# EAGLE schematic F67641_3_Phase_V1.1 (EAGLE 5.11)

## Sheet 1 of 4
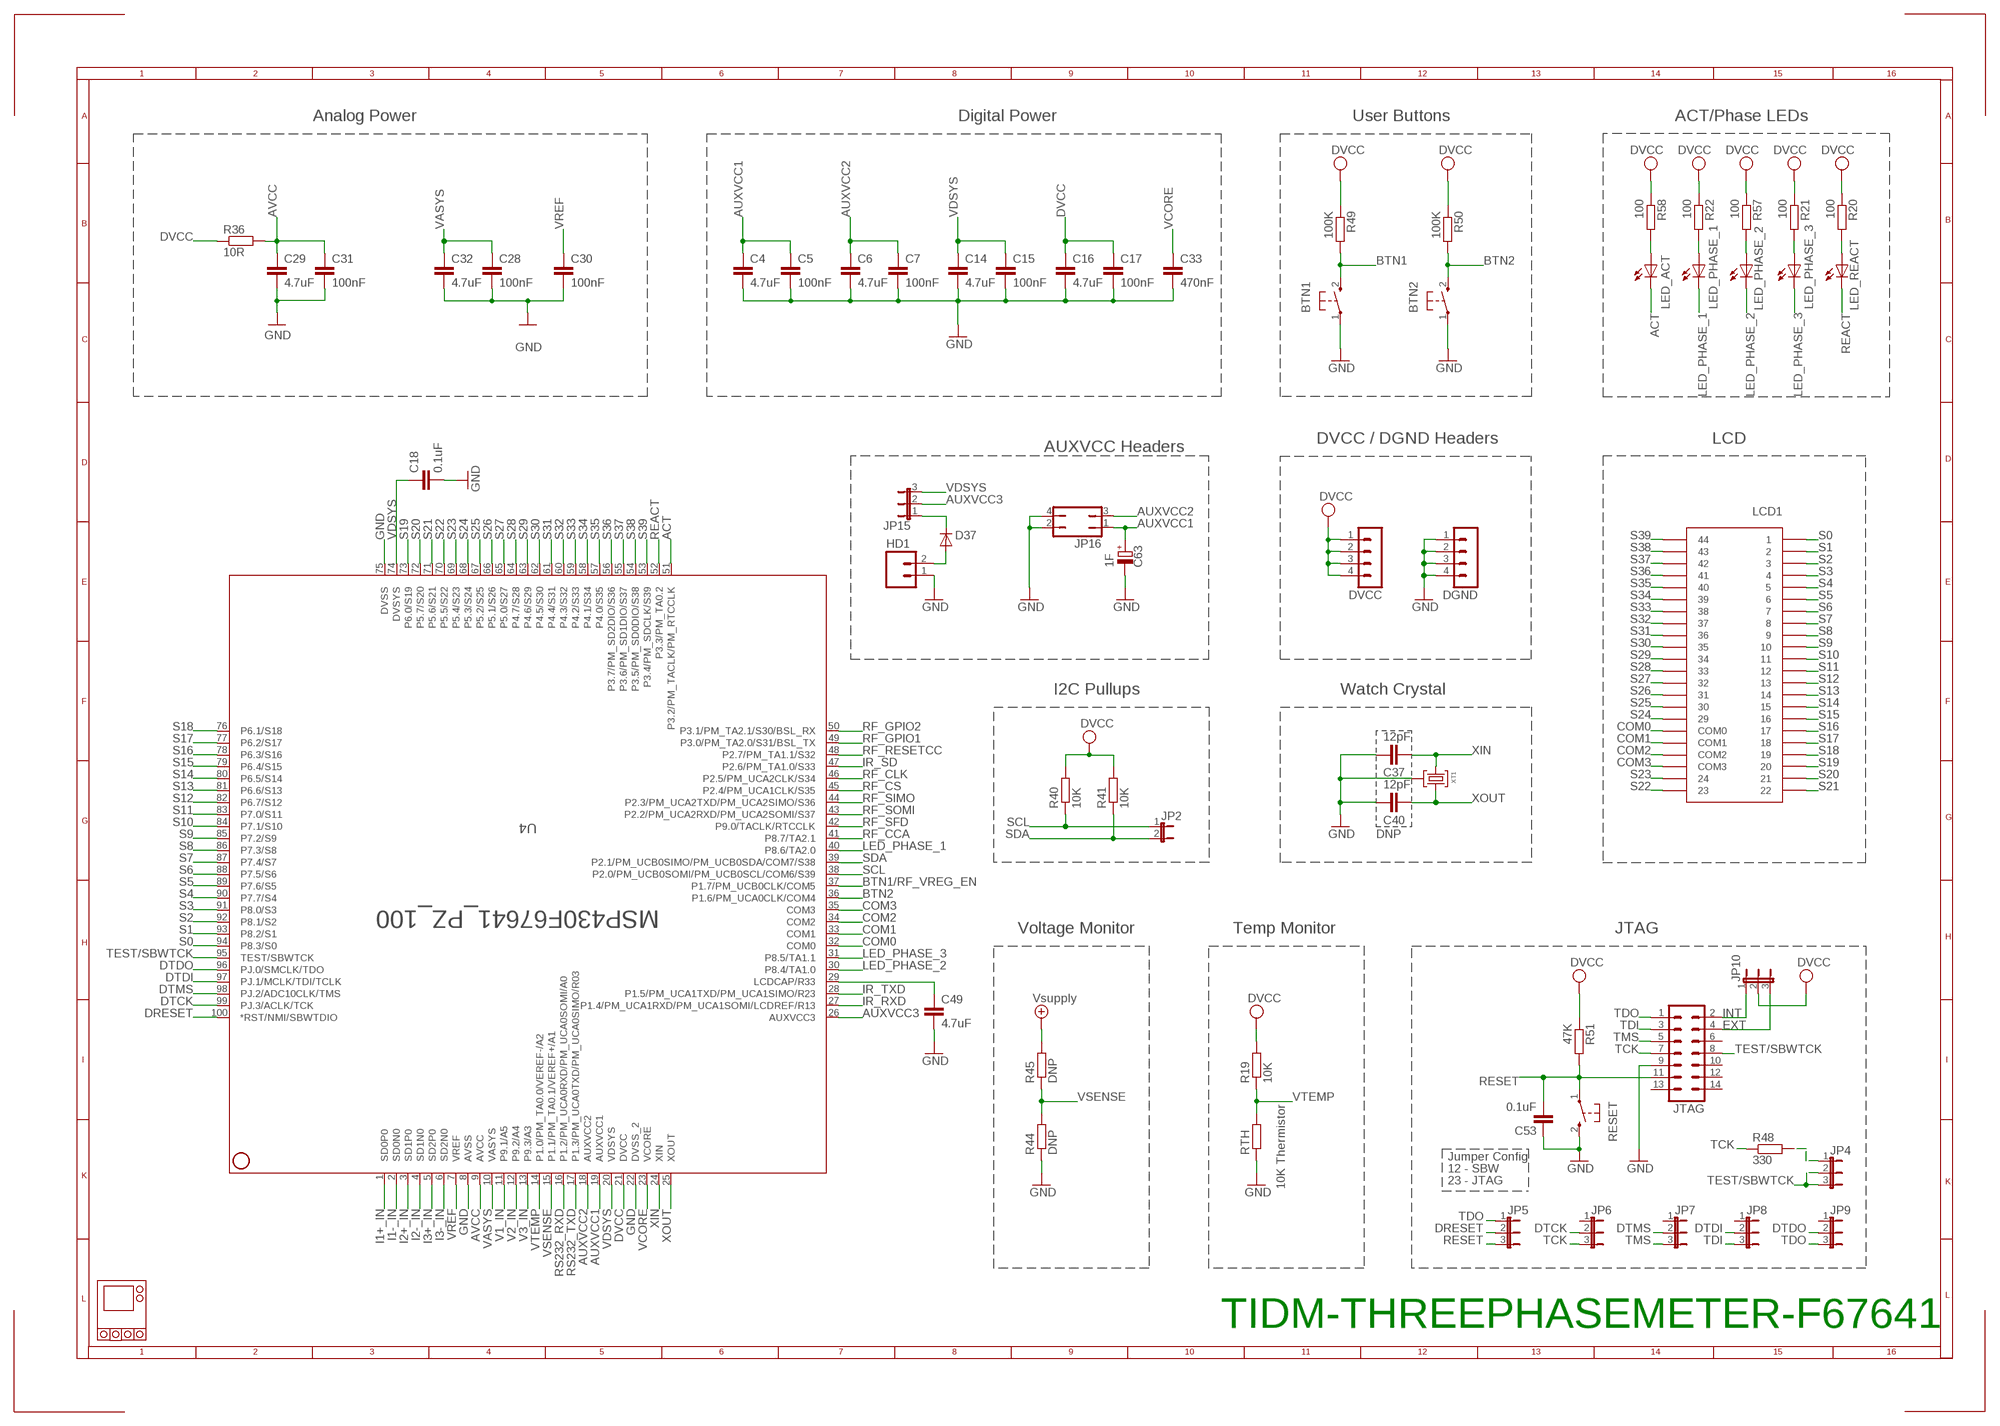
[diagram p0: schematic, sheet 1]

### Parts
BTN1  PB  [PBTH]
BTN2  PB  [PBTH]
C4  4.7uF  C-EUC0603  [C0603]
C5  100nF  C-EUC0603  [C0603]
C6  4.7uF  C-EUC0603  [C0603]
C7  100nF  C-EUC0603  [C0603]
C14  4.7uF  C-EUC0603  [C0603]
C15  100nF  C-EUC0603  [C0603]
C16  4.7uF  C-EUC0603  [C0603]
C17  100nF  C-EUC0603  [C0603]
C18  0.1uF  C-EUC0603  [C0603]
C28  100nF  C-EUC0603  [C0603]
C29  4.7uF  C-EUC0603  [C0603]
C30  100nF  C-EUC0603  [C0603]
C31  100nF  C-EUC0603  [C0603]
C32  4.7uF  C-EUC0603  [C0603]
C33  470nF  C-EUC0603  [C0603]
C37  12pF  C-EUC0603  [C0603]
C40  12pF  C-EUC0603  [C0603]
C49  4.7uF  C-EUC0603  [C0603]
C53  0.1uF  C-EUC0603  [C0603]
C63  1F  SUPERCAP  [SUPERCAP]
CASE1  3_PHASE_CASE  [3_PHASE_CASE]
D37  PMLL4148  [SOD80C]
DGND  MA04-1  [MA04-1]
DVCC  MA04-1  [MA04-1]
HD1  M02PTH  [1X02]
JP2  JP1E  [JP1]
JP4  JP2E  [JP2]
JP5  JP2E  [JP2]
JP6  JP2E  [JP2]
JP7  JP2E  [JP2]
JP8  JP2E  [JP2]
JP9  JP2E  [JP2]
JP10  JP2E  [JP2]
JP15  JP2E  [JP2]
JP16  JP2Q  [JP2Q]
JTAG  ML14  [ML14]
LCD1  TI_160SEG_LCD  [TI_160SEG_LCD]
LED_ACT  LED3MM  [LED3MM]
LED_PHASE_1  LED3MM  [LED3MM]
LED_PHASE_2  LED3MM  [LED3MM]
LED_PHASE_3  LED3MM  [LED3MM]
LED_REACT  LED3MM  [LED3MM]
R19  10K  R-EU_R0603  [R0603]
R20  100  R-EU_R0603  [R0603]
R21  100  R-EU_R0603  [R0603]
R22  100  R-EU_R0603  [R0603]
R36  10R  R-EU_R0805  [R0805]
R40  10K  R-EU_R0603  [R0603]
R41  10K  R-EU_R0603  [R0603]
R44  DNP  R-EU_R0603  [R0603]
R45  DNP  R-EU_R0603  [R0603]
R48  330  R-EU_R0603  [R0603]
R49  100K  R-EU_R0603  [R0603]
R50  100K  R-EU_R0603  [R0603]
R51  47K  R-EU_R0603  [R0603]
R57  100  R-EU_R0603  [R0603]
R58  100  R-EU_R0603  [R0603]
RESET  PB  [PBTH]
RTH  10K Thermistor  R-EU_R0603  [R0603]
U4  MSP430F67641_PZ_100  [PZ100]
XT1  CM200T  [CM200T]

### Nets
ACT: LED_ACT.K(C) U4.51(P3.2/PM_TACLK/PM_RTCCLK) ; also sheet 4
AUXVCC1: C4.1 C5.1 C63.VCC(+) JP16.1 U4.19(AUXVCC1)
AUXVCC2: C6.1 C7.1 JP16.3 U4.18(AUXVCC2)
AUXVCC3: JP15.2 U4.26(AUXVCC3)
AVCC: C29.1 C31.1 R36.2 U4.9(AVCC) ; also sheet 2
BTN1: BTN1.2(S) R49.2 ; also sheet 4
BTN1/RF_VREG_EN: U4.37(P1.7/PM_UCB0CLK/COM5) ; also sheet 4
BTN2: BTN2.2(S) R50.2 U4.36(P1.6/PM_UCA0CLK/COM4)
COM0: LCD1.COM0 U4.32(COM0)
COM1: LCD1.COM1 U4.33(COM1)
COM2: LCD1.COM2 U4.34(COM2)
COM3: LCD1.COM3 U4.35(COM3)
DRESET: JP5.2 U4.100(*RST/NMI/SBWTDIO)
DTCK: JP6.2 U4.99(PJ.3/ACLK/TCK)
DTDI: JP8.2 U4.97(PJ.1/MCLK/TDI/TCLK)
DTDO: JP9.2 U4.96(PJ.0/SMCLK/TDO)
DTMS: JP7.2 U4.98(PJ.2/ADC10CLK/TMS)
DVCC: C16.1 C17.1 DVCC.1 DVCC.2 DVCC.3 DVCC.4 JP10.2 R19.2 R20.1 R21.1 R22.1 R36.1 R40.2 R41.2 R49.1 R50.1 R51.1 R57.1 R58.1 U4.21(DVCC) ; also sheet 3,4
EXT: JP10.3 JTAG.4
GND: BTN1.1(P) BTN2.1(P) C4.2 C5.2 C6.2 C7.2 C14.2 C15.2 C16.2 C17.2 C18.2 C28.2 C29.2 C30.2 C31.2 C32.2 C33.2 C37.2 C40.2 C49.2 C53.1 C63.GND(-) DGND.1 DGND.2 DGND.3 DGND.4 HD1.1 JP16.2 JP16.4 JTAG.9 R44.1 RESET.2(S) RTH.1 U4.8(AVSS) U4.22(DVSS_2) U4.75(DVSS) XT1.P3 ; also sheet 2,3,4
I1+_IN: U4.1(SD0P0) ; also sheet 2
I1-_IN: U4.2(SD0N0) ; also sheet 2
I2+_IN: U4.3(SD1P0) ; also sheet 2
I2-_IN: U4.4(SD1N0) ; also sheet 2
I3+_IN: U4.5(SD2P0) ; also sheet 2
I3-_IN: U4.6(SD2N0) ; also sheet 2
INT: JP10.1 JTAG.2
IR_RXD: U4.27(P1.4/PM_UCA1RXD/PM_UCA1SOMI/LCDREF/R13) ; also sheet 4
IR_SD: U4.47(P2.6/PM_TA1.0/S33) ; also sheet 4
IR_TXD: U4.28(P1.5/PM_UCA1TXD/PM_UCA1SIMO/R23) ; also sheet 4
LED_PHASE_1: LED_PHASE_1.K(C) U4.40(P8.6/TA2.0)
LED_PHASE_2: LED_PHASE_2.K(C) U4.30(P8.4/TA1.0)
LED_PHASE_3: LED_PHASE_3.K(C) U4.31(P8.5/TA1.1)
N$4: C49.1 U4.29(LCDCAP/R33)
N$5: LED_REACT.A R20.2
N$6: LED_PHASE_3.A R21.2
N$7: LED_PHASE_1.A R22.2
N$10: JP4.1 R48.2
N$33: D37.C JP15.1
N$34: D37.A HD1.2
N$44: LED_ACT.A R58.2
N$46: LED_PHASE_2.A R57.2
REACT: LED_REACT.K(C) U4.52(P3.3/PM_TA0.2) ; also sheet 4
RESET: C53.2 JP5.3 JTAG.11 R51.2 RESET.1(P)
RF_CCA: U4.41(P8.7/TA2.1) ; also sheet 4
RF_CLK: U4.46(P2.5/PM_UCA2CLK/S34) ; also sheet 4
RF_CS: U4.45(P2.4/PM_UCA1CLK/S35) ; also sheet 4
RF_GPIO1: U4.49(P3.0/PM_TA2.0/S31/BSL_TX) ; also sheet 4
RF_GPIO2: U4.50(P3.1/PM_TA2.1/S30/BSL_RX) ; also sheet 4
RF_RESETCC: U4.48(P2.7/PM_TA1.1/S32) ; also sheet 4
RF_SFD: U4.42(P9.0/TACLK/RTCCLK) ; also sheet 4
RF_SIMO: U4.44(P2.3/PM_UCA2TXD/PM_UCA2SIMO/S36) ; also sheet 4
RF_SOMI: U4.43(P2.2/PM_UCA2RXD/PM_UCA2SOMI/S37) ; also sheet 4
RS232_RXD: U4.16(P1.2/PM_UCA0RXD/PM_UCA0SOMI/A0) ; also sheet 4
RS232_TXD: U4.17(P1.3/PM_UCA0TXD/PM_UCA0SIMO/R03) ; also sheet 4
S0: LCD1.1 U4.94(P8.3/S0)
S1: LCD1.2 U4.93(P8.2/S1)
S2: LCD1.3 U4.92(P8.1/S2)
S3: LCD1.4 U4.91(P8.0/S3)
S4: LCD1.5 U4.90(P7.7/S4)
S5: LCD1.6 U4.89(P7.6/S5)
S6: LCD1.7 U4.88(P7.5/S6)
S7: LCD1.8 U4.87(P7.4/S7)
S8: LCD1.9 U4.86(P7.3/S8)
S9: LCD1.10 U4.85(P7.2/S9)
S10: LCD1.11 U4.84(P7.1/S10)
S11: LCD1.12 U4.83(P7.0/S11)
S12: LCD1.13 U4.82(P6.7/S12)
S13: LCD1.14 U4.81(P6.6/S13)
S14: LCD1.15 U4.80(P6.5/S14)
S15: LCD1.16 U4.79(P6.4/S15)
S16: LCD1.17 U4.78(P6.3/S16)
S17: LCD1.18 U4.77(P6.2/S17)
S18: LCD1.19 U4.76(P6.1/S18)
S19: LCD1.20 U4.73(P6.0/S19)
S20: LCD1.21 U4.72(P5.7/S20)
S21: LCD1.22 U4.71(P5.6/S21)
S22: LCD1.23 U4.70(P5.5/S22)
S23: LCD1.24 U4.69(P5.4/S23)
S24: LCD1.29 U4.68(P5.3/S24)
S25: LCD1.30 U4.67(P5.2/S25)
S26: LCD1.31 U4.66(P5.1/S26)
S27: LCD1.32 U4.65(P5.0/S27)
S28: LCD1.33 U4.64(P4.7/S28)
S29: LCD1.34 U4.63(P4.6/S29)
S30: LCD1.35 U4.62(P4.5/S30)
S31: LCD1.36 U4.61(P4.4/S31)
S32: LCD1.37 U4.60(P4.3/S32)
S33: LCD1.38 U4.59(P4.2/S33)
S34: LCD1.39 U4.58(P4.1/S34)
S35: LCD1.40 U4.57(P4.0/S35)
S36: LCD1.41 U4.56(P3.7/PM_SD2DIO/S36)
S37: LCD1.42 U4.55(P3.6/PM_SD1DIO/S37)
S38: LCD1.43 U4.54(P3.5/PM_SD0DIO/S38)
S39: LCD1.44 U4.53(P3.4/PM_SDCLK/S39)
SCL: JP2.1 R40.1 U4.38(P2.0/PM_UCB0SOMI/PM_UCB0SCL/COM6/S39) ; also sheet 4
SDA: JP2.2 R41.1 U4.39(P2.1/PM_UCB0SIMO/PM_UCB0SDA/COM7/S38) ; also sheet 4
TCK: JP6.3 JTAG.7 R48.1
TDI: JP8.3 JTAG.3
TDO: JP5.1 JP9.3 JTAG.1
TEST/SBWTCK: JP4.2 JP4.3 JTAG.8 U4.95(TEST/SBWTCK)
TMS: JP7.3 JTAG.5
V1_IN: U4.11(P9.1/A5) ; also sheet 2
V2_IN: U4.12(P9.2/A4) ; also sheet 2
V3_IN: U4.13(P9.3/A3) ; also sheet 2
VASYS: C28.1 C32.1 U4.10(VASYS)
VCORE: C33.1 U4.23(VCORE)
VDSYS: C14.1 C15.1 C18.1 JP15.3 U4.20(VDSYS) U4.74(DVSYS)
VREF: C30.1 U4.7(VREF)
VSENSE: R44.2 R45.1 U4.15(P1.1/PM_TA0.1/VEREF+/A1)
VSUPPLY: R45.2 ; supply symbol labelled Vsupply ; also sheet 3
VTEMP: R19.1 RTH.2 U4.14(P1.0/PM_TA0.0/VEREF-/A2)
XIN: C37.1 U4.24(XIN) XT1.P2
XOUT: C40.1 U4.25(XOUT) XT1.P1
Unconnected: JP6.1 JP7.1 JP8.1 JP9.1 JTAG.6 JTAG.10 JTAG.12 JTAG.13 JTAG.14

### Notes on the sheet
- Analog Power | Digital Power | User Buttons | ACT/Phase LEDs
- DVCC / DGND Headers | LCD
- AUXVCC Headers
- I2C Pullups | Watch Crystal
- DNP
- Voltage Monitor | Temp Monitor | JTAG
- Jumper Config
- 12 - SBW
- 23 - JTAG
- TIDM-THREEPHASEMETER-F67641

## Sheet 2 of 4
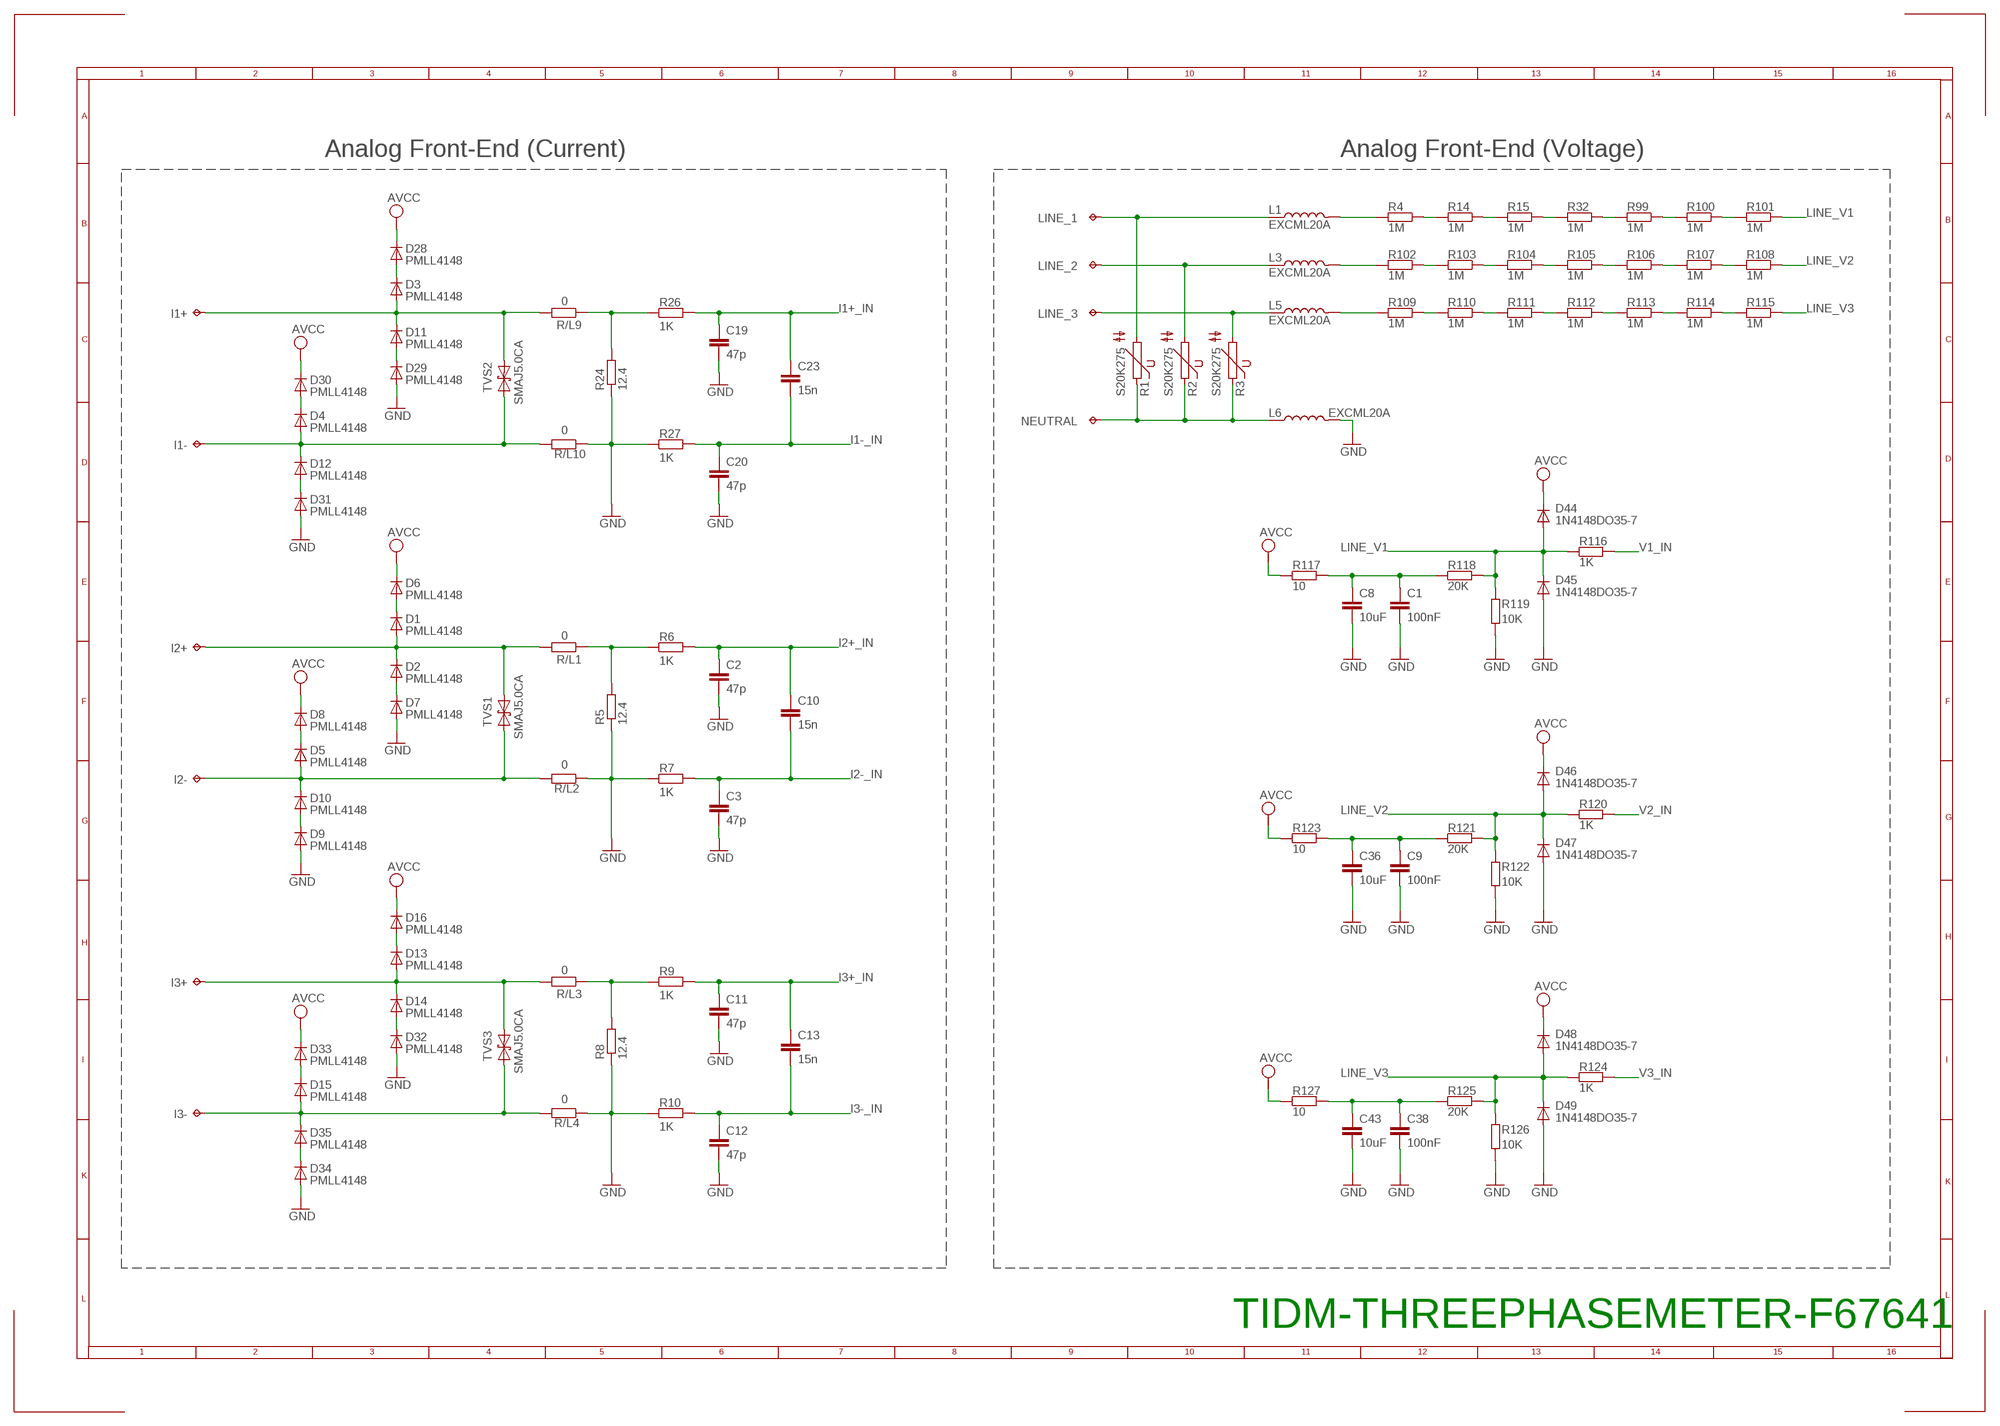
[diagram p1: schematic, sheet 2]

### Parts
C1  100nF  C-EUC0805  [C0805]
C2  47p  C-EUC0805  [C0805]
C3  47p  C-EUC0805  [C0805]
C8  10uF  C-EUC0805  [C0805]
C9  100nF  C-EUC0805  [C0805]
C10  15n  C-EUC0805  [C0805]
C11  47p  C-EUC0805  [C0805]
C12  47p  C-EUC0805  [C0805]
C13  15n  C-EUC0805  [C0805]
C19  47p  C-EUC0805  [C0805]
C20  47p  C-EUC0805  [C0805]
C23  15n  C-EUC0805  [C0805]
C36  10uF  C-EUC0805  [C0805]
C38  100nF  C-EUC0805  [C0805]
C43  10uF  C-EUC0805  [C0805]
D1  PMLL4148  [SOD80C]
D2  PMLL4148  [SOD80C]
D3  PMLL4148  [SOD80C]
D4  PMLL4148  [SOD80C]
D5  PMLL4148  [SOD80C]
D6  PMLL4148  [SOD80C]
D7  PMLL4148  [SOD80C]
D8  PMLL4148  [SOD80C]
D9  PMLL4148  [SOD80C]
D10  PMLL4148  [SOD80C]
D11  PMLL4148  [SOD80C]
D12  PMLL4148  [SOD80C]
D13  PMLL4148  [SOD80C]
D14  PMLL4148  [SOD80C]
D15  PMLL4148  [SOD80C]
D16  PMLL4148  [SOD80C]
D28  PMLL4148  [SOD80C]
D29  PMLL4148  [SOD80C]
D30  PMLL4148  [SOD80C]
D31  PMLL4148  [SOD80C]
D32  PMLL4148  [SOD80C]
D33  PMLL4148  [SOD80C]
D34  PMLL4148  [SOD80C]
D35  PMLL4148  [SOD80C]
D44  1N4148DO35-7  DIODE-SOD523  [SOD523]
D45  1N4148DO35-7  DIODE-SOD523  [SOD523]
D46  1N4148DO35-7  DIODE-SOD523  [SOD523]
D47  1N4148DO35-7  DIODE-SOD523  [SOD523]
D48  1N4148DO35-7  DIODE-SOD523  [SOD523]
D49  1N4148DO35-7  DIODE-SOD523  [SOD523]
I1+  TPPAD1-20  [P1-20]
I1-  TPPAD1-20  [P1-20]
I2+  TPPAD1-20  [P1-20]
I2-  TPPAD1-20  [P1-20]
I3+  TPPAD1-20  [P1-20]
I3-  TPPAD1-20  [P1-20]
L1  EXCML20A  EXCELSA390805  [R0805]
L3  EXCML20A  EXCELSA390805  [R0805]
L5  EXCML20A  EXCELSA390805  [R0805]
L6  EXCML20A  EXCELSA390805  [R0805]
LINE_1  TPPAD1-20  [P1-20]
LINE_2  TPPAD1-20  [P1-20]
LINE_3  TPPAD1-20  [P1-20]
NEUTRAL  TPPAD1-20  [P1-20]
R1  S20K275  [S20K275]
R2  S20K275  [S20K275]
R3  S20K275  [S20K275]
R4  1M  R-EU_R0805  [R0805]
R5  12.4  R-EU_R0805  [R0805]
R6  1K  R-EU_R0805  [R0805]
R7  1K  R-EU_R0805  [R0805]
R8  12.4  R-EU_R0805  [R0805]
R9  1K  R-EU_R0805  [R0805]
R10  1K  R-EU_R0805  [R0805]
R14  1M  R-EU_R0805  [R0805]
R15  1M  R-EU_R0805  [R0805]
R24  12.4  R-EU_R0805  [R0805]
R26  1K  R-EU_R0805  [R0805]
R27  1K  R-EU_R0805  [R0805]
R32  1M  R-EU_R0805  [R0805]
R99  1M  R-EU_R0805  [R0805]
R100  1M  R-EU_R0805  [R0805]
R101  1M  R-EU_R0805  [R0805]
R102  1M  R-EU_R0805  [R0805]
R103  1M  R-EU_R0805  [R0805]
R104  1M  R-EU_R0805  [R0805]
R105  1M  R-EU_R0805  [R0805]
R106  1M  R-EU_R0805  [R0805]
R107  1M  R-EU_R0805  [R0805]
R108  1M  R-EU_R0805  [R0805]
R109  1M  R-EU_R0805  [R0805]
R110  1M  R-EU_R0805  [R0805]
R111  1M  R-EU_R0805  [R0805]
R112  1M  R-EU_R0805  [R0805]
R113  1M  R-EU_R0805  [R0805]
R114  1M  R-EU_R0805  [R0805]
R115  1M  R-EU_R0805  [R0805]
R116  1K  R-EU_R0805  [R0805]
R117  10  R-EU_R0805  [R0805]
R118  20K  R-EU_R0805  [R0805]
R119  10K  R-EU_R0805  [R0805]
R120  1K  R-EU_R0805  [R0805]
R121  20K  R-EU_R0805  [R0805]
R122  10K  R-EU_R0805  [R0805]
R123  10  R-EU_R0805  [R0805]
R124  1K  R-EU_R0805  [R0805]
R125  20K  R-EU_R0805  [R0805]
R126  10K  R-EU_R0805  [R0805]
R127  10  R-EU_R0805  [R0805]
R/L1  0  R-EU_R0805  [R0805]
R/L2  0  R-EU_R0805  [R0805]
R/L3  0  R-EU_R0805  [R0805]
R/L4  0  R-EU_R0805  [R0805]
R/L9  0  R-EU_R0805  [R0805]
R/L10  0  R-EU_R0805  [R0805]
TVS1  SMAJ5.0CA  [DO214AC]
TVS2  SMAJ5.0CA  [DO214AC]
TVS3  SMAJ5.0CA  [DO214AC]

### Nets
AVCC: D6.C D8.C D16.C D28.C D30.C D33.C D44.C D46.C D48.C R117.1 R123.1 R127.1 ; also sheet 1
CUR1+: D3.A D11.C I1+.TP R/L9.2 TVS2.C(K)
CUR1+1: D1.A D2.C I2+.TP R/L1.2 TVS1.C(K)
CUR1+2: D13.A D14.C I3+.TP R/L3.2 TVS3.C(K)
CUR1-: D4.A D12.C I1-.TP R/L10.2 TVS2.A
CUR1-1: D5.A D10.C I2-.TP R/L2.2 TVS1.A
CUR1-2: D15.A D35.C I3-.TP R/L4.2 TVS3.A
GND: C1.2 C2.2 C3.2 C8.2 C9.2 C11.2 C12.2 C19.2 C20.2 C36.2 C38.2 C43.2 D7.A D9.A D29.A D31.A D32.A D34.A D45.A D47.A D49.A L6.2 R5.1 R7.1 R8.1 R10.1 R24.1 R27.1 R119.1 R122.1 R126.1 R/L2.1 R/L4.1 R/L10.1 ; also sheet 1,3,4
I1+_IN: C19.1 C23.1 R26.2 ; also sheet 1
I1-_IN: C20.1 C23.2 R27.2 ; also sheet 1
I2+_IN: C2.1 C10.1 R6.2 ; also sheet 1
I2-_IN: C3.1 C10.2 R7.2 ; also sheet 1
I3+_IN: C11.1 C13.1 R9.2 ; also sheet 1
I3-_IN: C12.1 C13.2 R10.2 ; also sheet 1
LINE_1: L1.1 LINE_1.TP R1.2 ; also sheet 3
LINE_2: L3.1 LINE_2.TP R2.2 ; also sheet 3
LINE_3: L5.1 LINE_3.TP R3.2 ; also sheet 3
LINE_V1: D44.A D45.C R101.1 R116.1 R118.2 R119.2
LINE_V2: D46.A D47.C R108.1 R120.1 R121.2 R122.2
LINE_V3: D48.A D49.C R115.1 R124.1 R125.2 R126.2
N$8: R5.2 R6.1 R/L1.1
N$13: D1.C D6.A
N$14: D5.C D8.A
N$15: D2.A D7.C
N$16: D9.C D10.A
N$19: R8.2 R9.1 R/L3.1
N$20: D3.C D28.A
N$21: D13.C D16.A
N$23: D11.A D29.C
N$25: D15.C D33.A
N$27: D14.A D32.C
N$29: D34.C D35.A
N$32: R24.2 R26.1 R/L9.1
N$39: D4.C D30.A
N$40: D12.A D31.C
N$96: R4.1 R14.2
N$97: R14.1 R15.2
N$98: R15.1 R32.2
N$99: R32.1 R99.2
N$100: R99.1 R100.2
N$101: R100.1 R101.2
N$102: R102.1 R103.2
N$103: R103.1 R104.2
N$104: R104.1 R105.2
N$105: R105.1 R106.2
N$106: R106.1 R107.2
N$107: R107.1 R108.2
N$108: R109.1 R110.2
N$109: R110.1 R111.2
N$110: R111.1 R112.2
N$111: R112.1 R113.2
N$112: R113.1 R114.2
N$113: R114.1 R115.2
N$114: L1.2 R4.2
N$115: L3.2 R102.2
N$116: L5.2 R109.2
N$117: C9.1 C36.1 R121.1 R123.2
N$118: C1.1 C8.1 R117.2 R118.1
N$119: C38.1 C43.1 R125.1 R127.2
NEUTRAL: L6.1 NEUTRAL.TP R1.1 R2.1 R3.1 ; also sheet 3
V1_IN: R116.2 ; also sheet 1
V2_IN: R120.2 ; also sheet 1
V3_IN: R124.2 ; also sheet 1

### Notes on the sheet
- Analog Front-End (Current) | Analog Front-End (Voltage)
- TIDM-THREEPHASEMETER-F67641

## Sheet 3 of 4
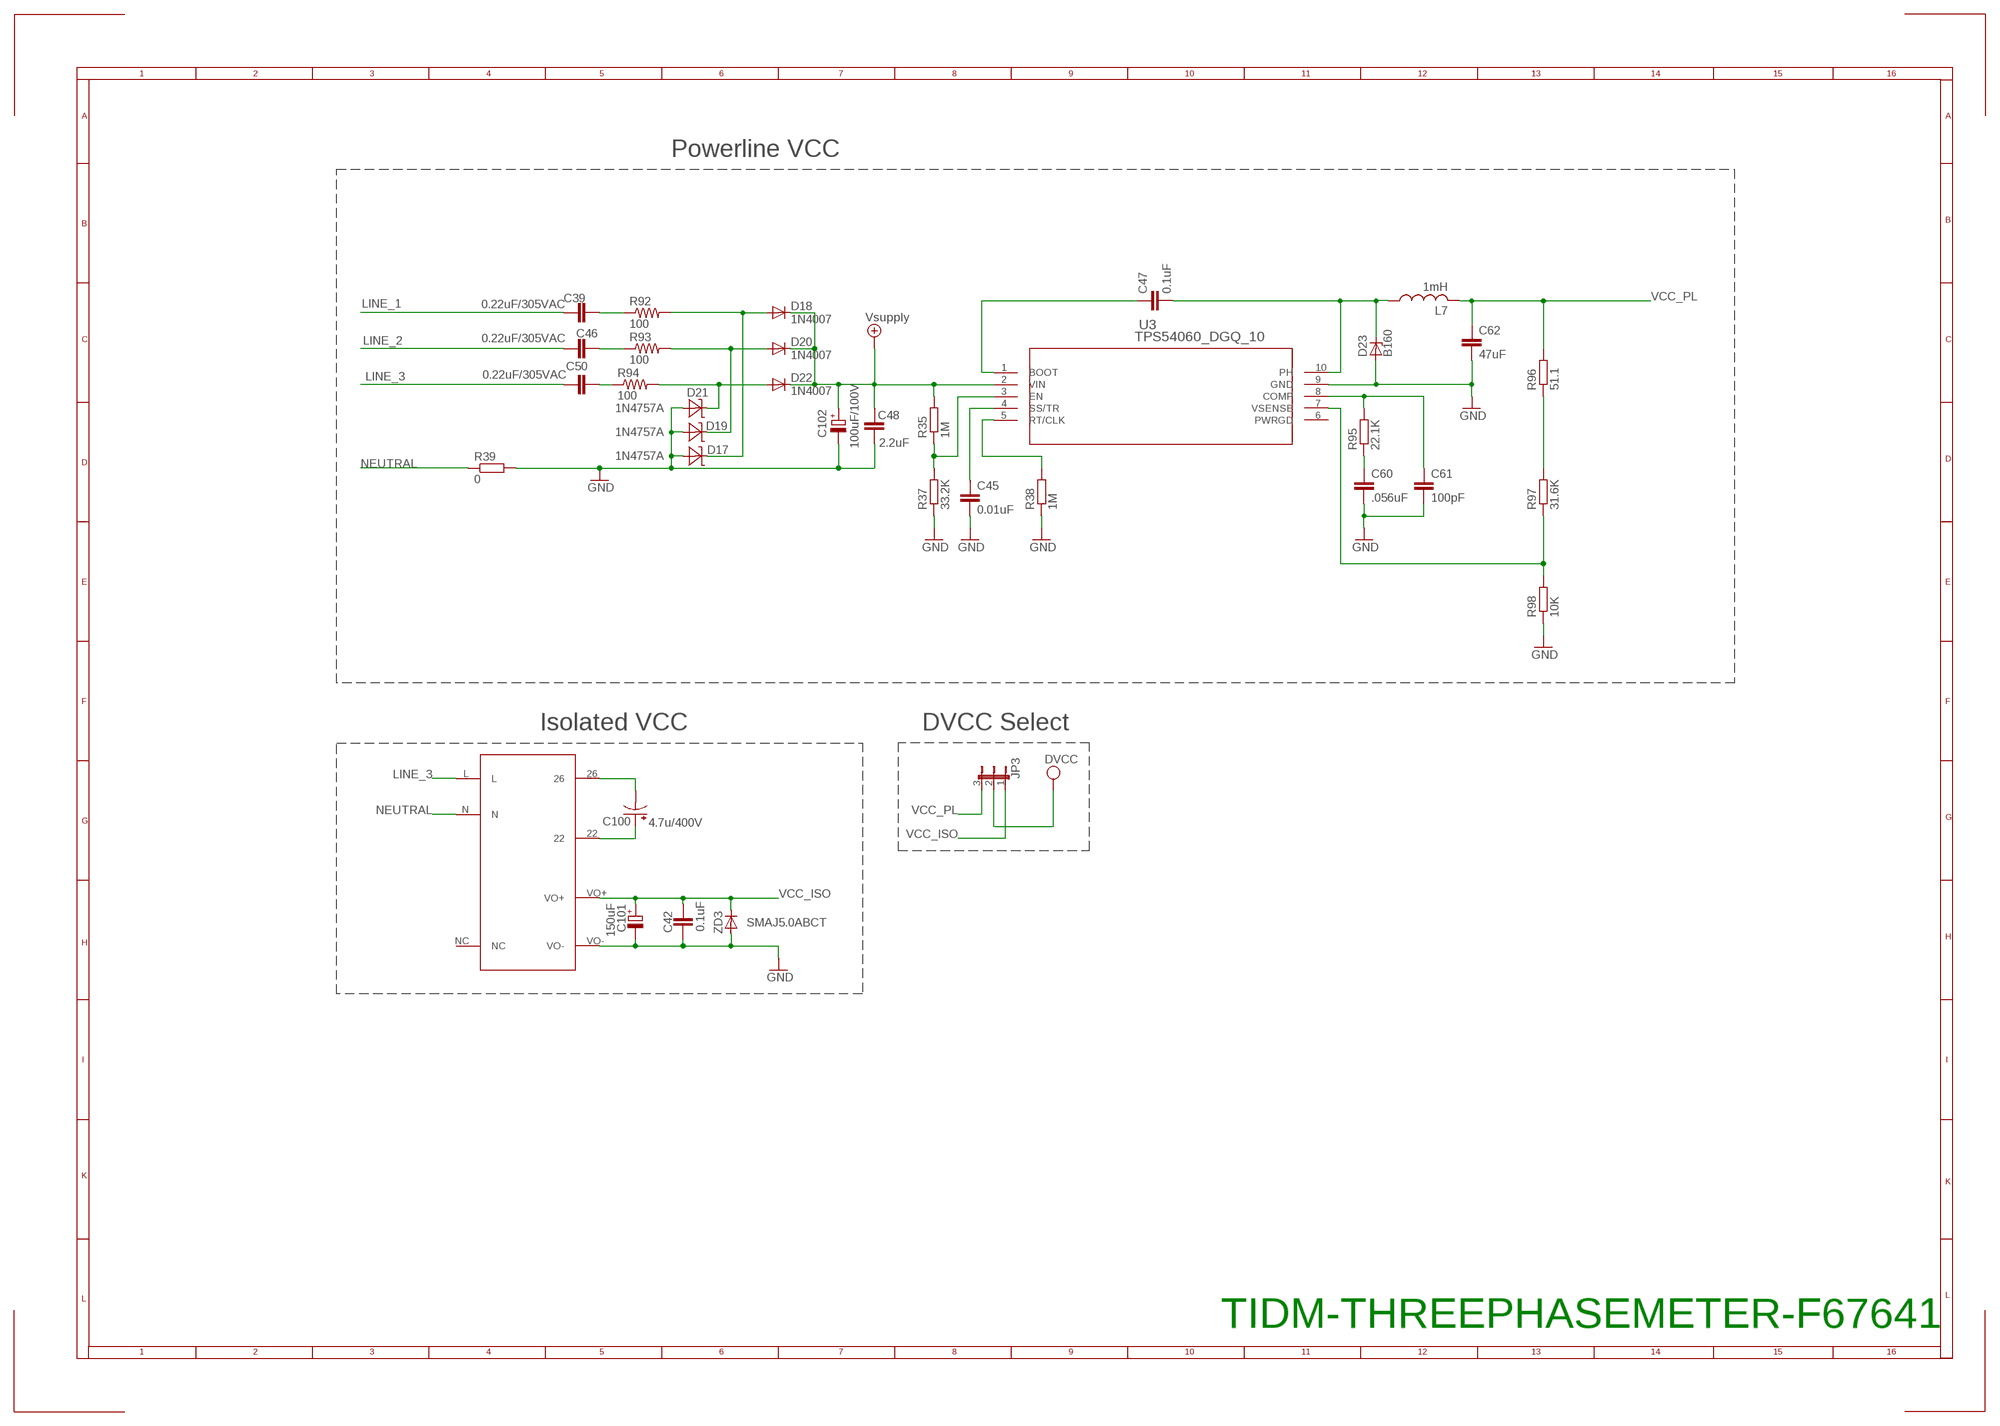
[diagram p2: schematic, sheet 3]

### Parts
C39  0.22uF/305VAC  C15/8  [C15B8]
C42  0.1uF  C-EUC0603  [C0603]
C45  0.01uF  C-EUC0603  [C0603]
C46  0.22uF/305VAC  C15/8  [C15B8]
C47  0.1uF  C-EUC0603  [C0603]
C48  2.2uF  C-EUC1210  [C1210]
C50  0.22uF/305VAC  C15/8  [C15B8]
C60  .056uF  C-EUC0603  [C0603]
C61  100pF  C-EUC0603  [C0603]
C62  47uF  C-EUC1210  [C1210]
C100  4.7u/400V  CPOL-USE5-10.5  [E5-10,5]
C101  150uF  CPOL-EUE2-5  [E2-5]
C102  100uF/100V  CPOL-EUE5-10.5  [E5-10,5]
D17  1N4757A  [DO41Z10]
D18  1N4007  [DO41-10]
D19  1N4757A  [DO41Z10]
D20  1N4007  [DO41-10]
D21  1N4757A  [DO41Z10]
D22  1N4007  [DO41-10]
D23  B160  ZENER-DIODESMB  [SMB]
JP3  JP2E  [JP2]
L7  1mH  L-USMSS1038-105  [INDUCTOR_POWER_SUPPLY_6779]
R35  1M  R-EU_R0603  [R0603]
R37  33.2K  R-EU_R0603  [R0603]
R38  1M  R-EU_R0603  [R0603]
R39  0  R-EU_R0805  [R0805]
R92  100  R-US_0414/15  [0414/15]
R93  100  R-US_0414/15  [0414/15]
R94  100  R-US_0414/15  [0414/15]
R95  22.1K  R-EU_R0603  [R0603]
R96  51.1  R-EU_R0603  [R0603]
R97  31.6K  R-EU_R0603  [R0603]
R98  10K  R-EU_R0603  [R0603]
U3  TPS54060_DGQ_10  [DGQ10_1P88X1P57]
U$1  CUI_XR  [CUI_XR]
ZD3  SMAJ5.0ABCT  DIODE-DO214AC  [DO214AC]

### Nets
DVCC: JP3.2 ; also sheet 1,4
GND: C42.2 C45.2 C48.2 C60.2 C61.2 C62.2 C101.- C102.- D17.A D19.A D21.A D23.A R37.1 R38.1 R39.2 R98.1 U3.9(GND) U$1.VO- ZD3.A ; also sheet 1,2,4
LINE_1: C39.1 ; also sheet 2
LINE_2: C46.1 ; also sheet 2
LINE_3: C50.1 U$1.L ; also sheet 2
N$1: C100.- U$1.26
N$2: C100.+ U$1.22
N$17: R38.2 U3.5(RT/CLK)
N$18: D17.C D18.A R92.2
N$37: C45.1 U3.4(SS/TR)
N$38: R35.1 R37.2 U3.3(EN)
N$47: D19.C D20.A R93.2
N$78: C47.1 U3.1(BOOT)
N$80: C47.2 D23.C L7.1 U3.10(PH)
N$82: C60.1 R95.1
N$84: C39.2 R92.1
N$89: C46.2 R93.1
N$90: C50.2 R94.1
N$92: C61.1 R95.2 U3.8(COMP)
N$93: R96.1 R97.2
N$94: D21.C D22.A R94.2
N$95: R97.1 R98.2 U3.7(VSENSE)
NEUTRAL: R39.1 U$1.N ; also sheet 2
VCC_ISO: C42.1 C101.+ JP3.1 U$1.VO+ ZD3.C
VCC_PL: C62.1 JP3.3 L7.2 R96.2
VSUPPLY: C48.1 C102.+ D18.C D20.C D22.C R35.2 U3.2(VIN) ; supply symbol labelled Vsupply ; also sheet 1
Unconnected: U3.6(PWRGD) U$1.NC

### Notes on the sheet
- Powerline VCC
- Isolated VCC | DVCC Select
- TIDM-THREEPHASEMETER-F67641

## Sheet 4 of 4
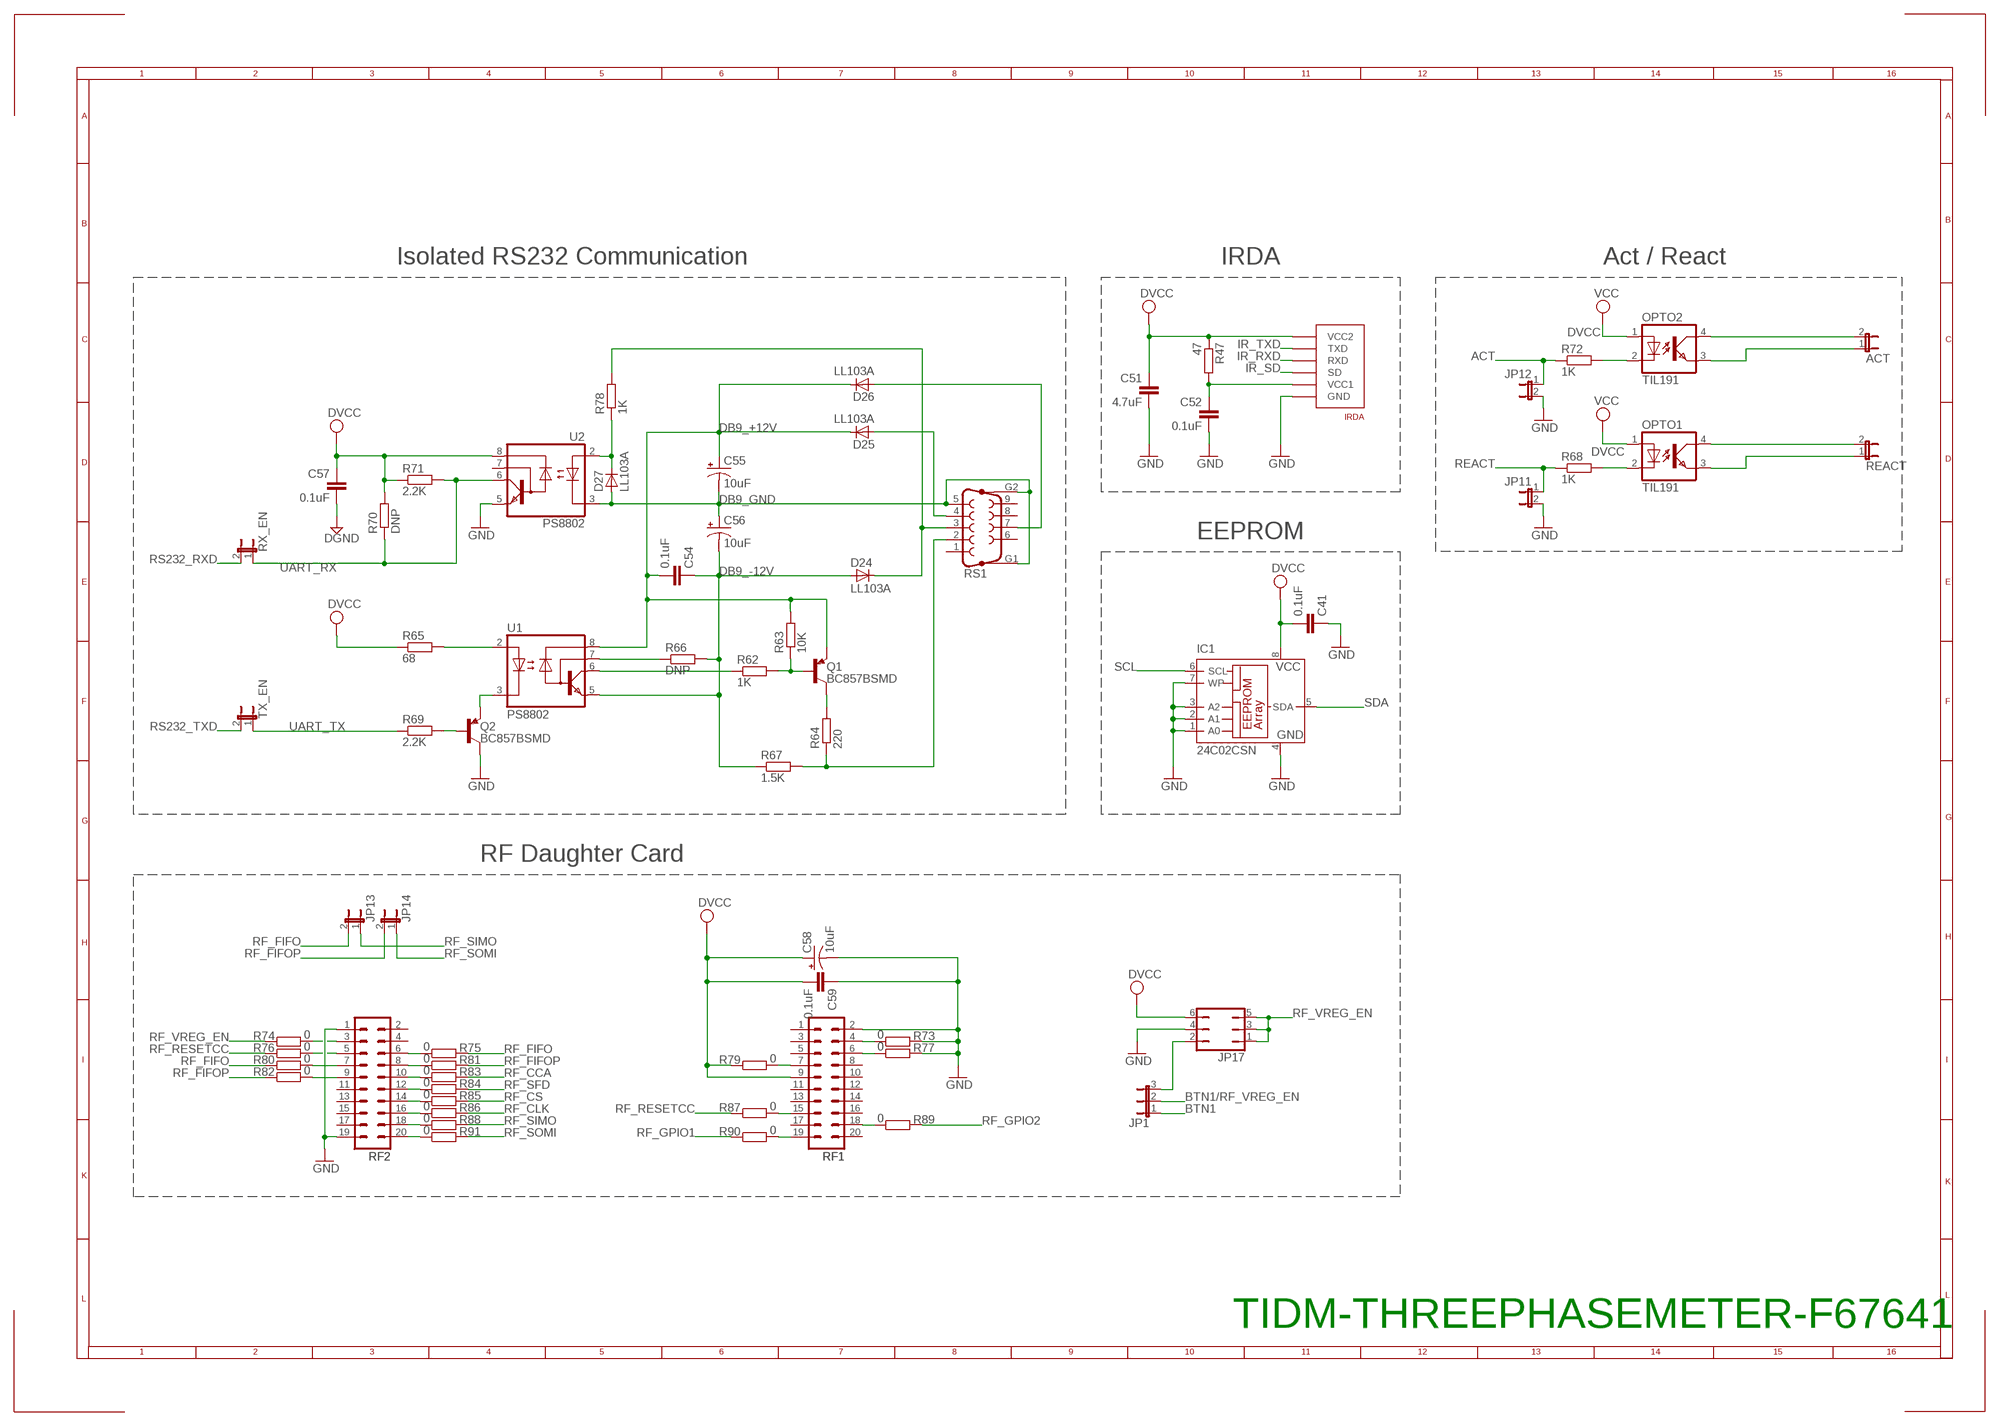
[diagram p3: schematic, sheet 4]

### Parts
ACT  JP1E  [JP1]
C41  0.1uF  C-EUC0603  [C0603]
C51  4.7uF  C-EUC0603  [C0603]
C52  0.1uF  C-EUC0603  [C0603]
C54  0.1uF  C-EUC0603  [C0603]
C55  10uF  CPOL-USCT3216  [CT3216]
C56  10uF  CPOL-USCT3216  [CT3216]
C57  0.1uF  C-EUC0603  [C0603]
C58  10uF  CPOL-USCT3216  [CT3216]
C59  0.1uF  C-EUC0603  [C0603]
D24  LL103A  D-SOD-80  [SOD80]
D25  LL103A  D-SOD-80  [SOD80]
D26  LL103A  D-SOD-80  [SOD80]
D27  LL103A  D-SOD-80  [SOD80]
IC1  24C02CSN  [SO-08]
IRDA  TFBS4711-TT1  [TFBS4711]
JP1  JP2E  [JP2]
JP11  JP1E  [JP1]
JP12  JP1E  [JP1]
JP13  JP1E  [JP1]
JP14  JP1E  [JP1]
JP17  JP3Q  [JP3Q]
OPTO1  TIL191  [DIL04]
OPTO2  TIL191  [DIL04]
Q1  BC857BSMD  [SOT23-BEC]
Q2  BC857BSMD  [SOT23-BEC]
R47  47  R-EU_R0603  [R0603]
R62  1K  R-EU_R0603  [R0603]
R63  10K  R-EU_R0603  [R0603]
R64  220  R-EU_R0603  [R0603]
R65  68  R-EU_R0603  [R0603]
R66  DNP  R-EU_R0603  [R0603]
R67  1.5K  R-EU_R0603  [R0603]
R68  1K  R-EU_R0603  [R0603]
R69  2.2K  R-EU_R0603  [R0603]
R70  DNP  R-EU_R0603  [R0603]
R71  2.2K  R-EU_R0603  [R0603]
R72  1K  R-EU_R0603  [R0603]
R73  0  R-EU_R0603  [R0603]
R74  0  R-EU_R0603  [R0603]
R75  0  R-EU_R0603  [R0603]
R76  0  R-EU_R0603  [R0603]
R77  0  R-EU_R0603  [R0603]
R78  1K  R-EU_R0603  [R0603]
R79  0  R-EU_R0603  [R0603]
R80  0  R-EU_R0603  [R0603]
R81  0  R-EU_R0603  [R0603]
R82  0  R-EU_R0603  [R0603]
R83  0  R-EU_R0603  [R0603]
R84  0  R-EU_R0603  [R0603]
R85  0  R-EU_R0603  [R0603]
R86  0  R-EU_R0603  [R0603]
R87  0  R-EU_R0603  [R0603]
R88  0  R-EU_R0603  [R0603]
R89  0  R-EU_R0603  [R0603]
R90  0  R-EU_R0603  [R0603]
R91  0  R-EU_R0603  [R0603]
REACT  JP1E  [JP1]
RF1  TFM-110-02-SM-D-A-K  [TFM-110-02-SM-D-A-K]
RF2  TFM-110-02-SM-D-A-K  [TFM-110-02-SM-D-A-K]
RS1  F09VP  [F09VP]
RX_EN  JP1E  [JP1]
TX_EN  JP1E  [JP1]
U1  PS8802  [SO08]
U2  PS8802  [SO08]

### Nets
ACT: JP12.1 R72.1 ; also sheet 1
BTN1: JP1.1 ; also sheet 1
BTN1/RF_VREG_EN: JP1.2 ; also sheet 1
DB9_+12V: C54.2 C55.+ D25.1(C) D26.1(C) Q1.E R63.2 U1.8(VCC)
DB9_-12V: C54.1 C56.- D24.2(A) R66.2 R67.1 U1.5(GND)
DB9_GND: C55.- C56.+ D27.2(A) RS1.5 RS1.G1 RS1.G2 U2.3(C)
DVCC: C41.2 C51.1 C57.1 C58.+ C59.2 IC1.8(VCC) IRDA.P$1(VCC2) JP17.6 OPTO1.1(A) OPTO2.1(A) R47.1 R65.1 R70.2 R71.1 R79.1 RF1.9 U2.8(VCC) ; supply symbol labelled VCC ; also sheet 1,3
GND: C41.1 C51.2 C52.2 C57.2 C58.- C59.1 IC1.1(A0) IC1.2(A1) IC1.3(A2) IC1.4(GND) IC1.7(WP) IRDA.P$6(GND) JP11.2 JP12.2 JP17.4 Q2.C R73.2 R77.2 RF1.2 RF2.1 RF2.19 U2.5(GND) ; supply symbol labelled DGND ; also sheet 1,2,3
IR_RXD: IRDA.P$3(RXD) ; also sheet 1
IR_SD: IRDA.P$4(SD) ; also sheet 1
IR_TXD: IRDA.P$2(TXD) ; also sheet 1
N$3: ACT.2 OPTO2.4(COL)
N$9: R65.2 U1.2(A)
N$11: ACT.1 OPTO2.3(EMIT)
N$12: OPTO2.2(C) R72.2
N$22: Q2.B R69.2
N$24: R64.1 R67.2 RS1.2
N$26: R62.1 U1.6(VO)
N$28: Q1.B R62.2 R63.1
N$30: JP1.3 JP17.2
N$35: R74.2 RF2.3
N$41: Q1.C R64.2
N$43: R66.1 U1.7(VB)
N$45: R76.2 RF2.5
N$48: C52.1 IRDA.P$5(VCC1) R47.2
N$50: R79.2 RF1.7
N$51: R73.1 RF1.4
N$52: R87.2 RF1.15
N$53: R77.1 RF1.6
N$55: R83.1 RF2.10
N$56: R84.1 RF2.12
N$57: R85.1 RF2.14
N$58: D27.1(C) R78.1 U2.2(A)
N$59: R86.1 RF2.16
N$60: R88.1 RF2.18
N$61: R91.1 RF2.20
N$65: OPTO1.4(COL) REACT.2
N$67: D24.1(C) R78.2 RS1.3
N$68: OPTO1.3(EMIT) REACT.1
N$69: D26.2(A) RS1.7
N$71: D25.2(A) RS1.4
N$72: OPTO1.2(C) R68.2
N$79: Q2.E U1.3(C)
N$81: R90.2 RF1.19
N$83: R89.1 RF1.18
N$85: R80.2 RF2.7
N$86: R82.2 RF2.9
N$87: R81.1 RF2.8
N$88: R75.1 RF2.6
REACT: JP11.1 R68.1 ; also sheet 1
RF_CCA: R83.2 ; also sheet 1
RF_CLK: R86.2 ; also sheet 1
RF_CS: R85.2 ; also sheet 1
RF_FIFO: JP13.2 R75.2 R80.1
RF_FIFOP: JP14.2 R81.2 R82.1
RF_GPIO1: R90.1 ; also sheet 1
RF_GPIO2: R89.2 ; also sheet 1
RF_RESETCC: R76.1 R87.1 ; also sheet 1
RF_SFD: R84.2 ; also sheet 1
RF_SIMO: JP13.1 R88.2 ; also sheet 1
RF_SOMI: JP14.1 R91.2 ; also sheet 1
RF_VREG_EN: JP17.1 JP17.3 JP17.5 R74.1
RS232_RXD: RX_EN.2 ; also sheet 1
RS232_TXD: TX_EN.2 ; also sheet 1
SCL: IC1.6(SCL) ; also sheet 1
SDA: IC1.5(SDA) ; also sheet 1
UART_RX: R70.1 R71.2 RX_EN.1 U2.6(VO)
UART_TX: R69.1 TX_EN.1
Unconnected: RF1.1 RF1.3 RF1.5 RF1.8 RF1.10 RF1.11 RF1.12 RF1.13 RF1.14 RF1.16 RF1.17 RF1.20 RF2.2 RF2.4 RF2.11 RF2.13 RF2.15 RF2.17 RS1.1 RS1.6 RS1.8 RS1.9 U2.7(VB)

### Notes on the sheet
- Isolated RS232 Communication | IRDA | Act / React
- EEPROM
- RF Daughter Card
- TIDM-THREEPHASEMETER-F67641

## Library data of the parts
ACT JP2 JP11-JP14 REACT RX_EN TX_EN = custom_jumper:JP1E: JUMPER
BTN1 BTN2 RESET = electricalmeter:PB: OMRON SWITCH
C1-C3 C8-C13 C19 C20 C23 C36 C38 C41 C43 C45 C47 C51 C52 C54 C57 C62 = rcl:C-EU: CAPACITOR, European symbol
C4-C7 C14-C18 C28-C33 C37 C40 C42 C48 C49 C53 C59-C61 = resistor:C-EU: CAPACITOR, European symbol
C39 C46 C50 = capacitor-wima:C: CAPACITOR
C55 C56 = resistor:CPOL-US: POLARIZED CAPACITOR, American symbol
C58 C100 = rcl:CPOL-US: POLARIZED CAPACITOR, American symbol
C63 = supercap:SUPERCAP
C101 = rcl:CPOL-EU: POLARIZED CAPACITOR, European symbol
C102 = resistor:CPOL-EU: POLARIZED CAPACITOR, European symbol
CASE1 = meter_cases:3_PHASE_CASE
D1-D16 D28-D35 D37 = FE449x EVM:PMLL4148: DIODE
D17 D19 D21 = diode:1N4757A
D18 D20 D22 = diode:1N4007
D23 = diode:ZENER-DIODE: Z-Diode
D24-D27 = semicon-smd-ipc:D-: DIODE
D44-D49 ZD3 = diode:DIODE-: DIODE
DGND DVCC = custom_con-lstb:MA04-1: PIN HEADER; OC_FARNELL: unknown; OC_NEWARK: unknown
HD1 = SparkFun:M02: Header 2
I1+ I1- I2+ I2- I3+ I3- LINE_1-LINE_3 NEUTRAL = testpad:TP: Test pad
IC1 = microchip:24C*: Serial EEPROM 1 K/2 K/4 K; MF: MICROCHIP; MPN: 24C02C/SN; OC_FARNELL: 1607552; OC_NEWARK: 96K4065
IRDA = Personal:TFBS4711-TT1
JP1 JP15 = jumper:JP2E: JUMPER
JP3-JP10 = custom_jumper:JP2E: JUMPER
JP16 = jumper:JP2Q: JUMPER
JP17 = jumper:JP3Q: JUMPER
JTAG = con-ml:ML14: HARTING; OC_FARNELL: unknown; OC_NEWARK: unknown
L1 L3 L5 L6 = FE449x EVM:EXCELSA39: INDUCTOR
L7 = rcl:L-US: INDUCTOR, American symbol
LCD1 = Personal:TI_160SEG_LCD
LED_ACT LED_PHASE_1-LED_PHASE_3 LED_REACT = led:LED: LED
OPTO1 OPTO2 = optocoupler:TIL191: TEXAS INSTRUMENTS OPTO COUPLER; OC_FARNELL: 1683363; OC_NEWARK: unknown
Q1 Q2 = transistor-pnp:BC857*: PNP Transistror
R1-R3 = varistor:S20K275: VARISTOR
R4 R14 R15 R19-R22 R32 R44 R45 R48-R51 R57 R58 R99-R127 RTH = resistor:R-EU_: RESISTOR, European symbol
R5-R10 R24 R26 R27 R35-R41 R47 R62-R91 R95-R98 R/L1-R/L4 R/L9 R/L10 = rcl:R-EU_: RESISTOR, European symbol
R92-R94 = resistor:R-US_: RESISTOR, American symbol
RF1 RF2 = _MSP430:TFM-110-02-SM-D-A-K
RS1 = con-subd:F09VP: SUB-D; OC_FARNELL: unknown; OC_NEWARK: unknown
TVS1-TVS3 = FE449x EVM:SMAJ5.0CA
U1 U2 = FE449x EVM:PS8802: MOTOROLA OPTO COUPLER
U3 = TPS54060:TPS54060_DGQ_10; DATASHEETURL: http://www.ti.com/lit/gpn/TPS54060; DESCRIPTION: 3.5V to 60V Input, 0.5A Step-Down Converter with Eco-Mode; FAMILY_NAME: STEP-DOWN REGULATOR; GENERIC_PART_NUMBER: TPS54060; INDUSTRY_STD_PKG_TYPE: MSOP-PowerPAD; MANUFACTURER: Texas Instruments; MANUFACTURER_PART_NUMBER: tps54060_dgq_10; PACKAGE_DESIGNATOR: DGQ; PIN_COUNT: 10; VENDOR: Texas Instruments
U4 = F67641:MSP430F67641_PZ_100; DATASHEETURL: http://www.ti.com/lit/gpn/MSP430F67641; DESCRIPTION: MSP430F67641 Mixed Signal Microcontroller; FAMILY_NAME: 6 Series with LCD; GENERIC_PART_NUMBER: MSP430F67641; INDUSTRY_STD_PKG_TYPE: LQFP; MANUFACTURER: Texas Instruments; MANUFACTURER_PART_NUMBER: msp430f67641_pz_100; PACKAGE_DESIGNATOR: PZ; PIN_COUNT: 100; VENDOR: Texas Instruments
U$1 = TI_MSP430_v16_intern:CUI_XR
XT1 = F20xx PIR Demo & Eval:CM200T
